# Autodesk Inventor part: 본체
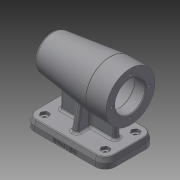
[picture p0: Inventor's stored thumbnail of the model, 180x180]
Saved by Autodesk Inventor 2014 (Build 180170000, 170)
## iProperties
Created: 2017-01
Part Number: 본체
Material: 일반
Document SubType Name: Modeling
Designer: USER
Density: 1 g/cm^3
Appearance: 기본값
Author: USER
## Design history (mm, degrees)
sketch "스케치1"
  geometry: L1 (0, 0)-(112, 0); L2 (112, 0)-(112, -70); L3 (112, -70)-(0, -70); L4 (0, -70)-(0, 0)
  constraints: 8 end point, 2 parallel, 1 horizontal, 1 perpendicular
  dimensions: "d0" = 112 distance of L1.start L1.end; "d1" = 70 distance of L3.end L1.start
extrude "돌출1" new body sketch "스케치1" distance "d2" = 14; taper "d3" = 0 deg
node "작업 평면1"
sketch "스케치3"
  geometry: L1 (0, 74)-(112, 74); L2 (0, 0)-(112, 0) reference; L3 (112, 74)-(112, 108); L4 (112, 108)-(84, 108); L5 (84, 108)-(3.73, 98.144); A1 r 80 centre (80, 74) between (3.73, 98.144) and (0, 74); 1 further point
  constraints: 8 end point, 2 perpendicular, 2 point on circle, 1 centre point, 1 horizontal, 1 point on line, 1 vertical alignment
  dimensions: "d16" = 74 distance between parallel lines of L2 L1; "d17" = 112 distance of L1.start L1.end; "d19" = 7 deg angle of L4 L5; "d20" = 28 distance of L3.end L4.end; "d21" = 68 diameter of L4 L1; "d26" = 80 distance of A1.centre L1.start
revolve "회전1" sketch "스케치3" stored, may be unused: angle "d27" = 90 deg
fillet "모깎기1" dims "d28" = 3
sketch "스케치4"
  geometry: C1 r 34 at (0, 0) reference; C2 r 21 at (0, 0); 1 further point
  constraints: 1 centre point, 1 coincident
  dimensions: "d29" = 42 diameter of C2
extrude "돌출2" cut sketch "스케치4" distance "d30" = 15; taper "d31" = 0 deg
sketch "스케치5"
  geometry: C1 r 21 at (0, 0) reference; C2 r 24 at (0, 0); 1 further point
  constraints: 1 centre point, 1 coincident
  dimensions: "d32" = 48 diameter of C2
extrude "돌출3" cut sketch "스케치5" distance "d33" = 54; taper "d34" = 0 deg
sketch "스케치6"
  geometry: C1 r 24 at (0, 0) reference; C2 r 21 at (0, 0); 1 further point
  constraints: 1 centre point, 1 coincident
  dimensions: "d35" = 42 diameter of C2
extrude "돌출4" cut sketch "스케치6" distance "d36" = 12; taper "d37" = 0 deg
sketch "스케치7"
  geometry: C1 r 21 at (0, 0) reference; C2 r 17.5 at (0, 0); 1 further point
  constraints: 1 centre point, 1 coincident
  dimensions: "d38" = 35 diameter of C2
extrude "돌출5" cut sketch "스케치7" distance "d39" = 18; taper "d40" = 0 deg
sketch "스케치8"
  geometry: C1 r 17.5 at (0, 0) reference; C2 r 16 at (0, 0); 1 further point
  constraints: 1 centre point, 1 coincident
  dimensions: "d41" = 32 diameter of C2
extrude "돌출6" cut sketch "스케치8" distance "d42" = 4; taper "d43" = 0 deg
sketch "스케치9"
  geometry: C1 r 16 at (0, 0) reference; C2 r 10.5 at (0, 0); 1 further point
  constraints: 1 centre point, 1 coincident
  dimensions: "d44" = 21 diameter of C2
extrude "돌출7" cut sketch "스케치9" distance "d45" = 3; taper "d46" = 0 deg
fillet "모깎기2" dims "d47" = 3
fillet "모깎기3" dims "d48" = 0.3
fillet "모깎기4" dims "d49" = 3
node "작업 평면2"
fillet "모깎기8" dims "d130" = 14
chamfer "모따기5" distance "d68" = 1; stored, may be unused: second distance "d69" = 2, angle "d70" = 45 deg
fillet "모깎기6" dims "d71" = 3
fillet "모깎기7" dims "d72" = 3
sketch "스케치14"
  geometry: C1 r 34 at (0, 0) reference; C2 r 22 at (0, 0) reference; A1 r 26 centre (0, 0) between (-26, 0) and (0, -26); 3 further points
  constraints: 4 point on circle, 2 horizontal alignment, 2 vertical alignment, 1 centre point, 1 coincident
  dimensions: "d73" = 52 diameter of A1
hole "구멍1" sketch "스케치14" at (-26, 0), (0, -26), (26, 0), (0, 26) diameter "d74" = 3.242; stored, may be unused: countersink angle "d78" = 90 deg, drill point angle "d80" = 118 deg; dims "d75" = 8, "d76" = 4, "d77" = 2, "d79" = 11
chamfer "모따기6" distance "d131" = 7; stored, may be unused: second distance "d132" = 2, angle "d133" = 15 deg
sketch "스케치22"
  geometry: L1 (14, -1.876)-(98, -1.876) reference; L2 (1.876, -56)-(1.876, -14) reference; L3 (18, -31)-(94, -31); L4 (94, -31)-(94, -39); L5 (94, -39)-(18, -39); L6 (18, -39)-(18, -31); 5 further points
  constraints: 8 end point, 4 midpoint, 2 parallel, 1 horizontal, 1 horizontal alignment, 1 perpendicular, 1 vertical alignment
  dimensions: "d134" = 76 distance of L3.start L3.end; "d135" = 8 distance of L5.end L3.start
extrude "돌출16" join sketch "스케치22" stored distance "d136" = 4; taper "d137" = 0 deg
node "작업 평면8"
sketch "스케치23"
  geometry: L1 (0, -17)-(0, 25) reference; L2 (0, -29.124)-(0, -17) reference; L3 (0, 25)-(0, 37.124) reference; L4 (0, -19)-(-38.397, -12.23); L5 (0, 27)-(-38.15, 20.273); L6 (14, -31)-(7, -31) reference; L7 (7, 39)-(14, 39) reference
  constraints: 4 end point, 2 point on line
  dimensions: "d138" = 12 distance from line of L6 L4.start; "d139" = 100 deg angle of L2 L4; "d140" = 100 deg angle of L3 L5; "d141" = 12 distance from line of L7 L5.start
feature "리브3" dims "d142" = 1, "d143" = 8, "d144" = 0, "d145" = 0, "d146" = 1, "d147" = 1
feature "리브4" dims "d148" = 1, "d149" = 8, "d150" = 0, "d151" = 0, "d152" = 1, "d153" = 1
fillet "모깎기9" dims "d154" = 1
fillet "모깎기10" dims "d155" = 3
fillet "모깎기11" dims "d156" = 3
sketch "스케치25"
  geometry: L1 (16.887, -9)-(19.774, -14); L2 (19.774, -14)-(16.887, -19); L3 (16.887, -19)-(11.113, -19); L4 (11.113, -19)-(8.226, -14); L5 (8.226, -14)-(11.113, -9); L6 (11.113, -9)-(16.887, -9); L7 (92.226, -14)-(95.113, -9); L8 (95.113, -9)-(100.887, -9); L9 (100.887, -9)-(103.774, -14); L10 (103.774, -14)-(100.887, -19); L11 (100.887, -19)-(95.113, -19); L12 (95.113, -19)-(92.226, -14); L13 (100.887, -51)-(103.774, -56); L14 (103.774, -56)-(100.887, -61); L15 (100.887, -61)-(95.113, -61); L16 (95.113, -61)-(92.226, -56); L17 (92.226, -56)-(95.113, -51); L18 (95.113, -51)-(100.887, -51); L19 (19.774, -56)-(16.887, -61); L20 (16.887, -61)-(11.113, -61); L21 (11.113, -61)-(8.226, -56); L22 (8.226, -56)-(11.113, -51); L23 (11.113, -51)-(16.887, -51); L24 (16.887, -51)-(19.774, -56); C1 r 5 at (14, -14); C2 r 5 at (98, -14); C3 r 5 at (14, -56); C4 r 5 at (98, -56); A1 r 11.357 centre (14, -56) between (2.643, -56) and (14, -67.357) reference; A2 r 11.357 centre (98, -56) between (98, -67.357) and (109.357, -56) reference; A3 r 11.357 centre (98, -14) between (109.357, -14) and (98, -2.643) reference; A4 r 11.357 centre (14, -14) between (14, -2.643) and (2.643, -14) reference; 9 further points
  constraints: 48 end point, 8 coincident, 4 centre point, 4 horizontal alignment, 4 midpoint, 4 tangent, 4 vertical alignment, 52 other
  dimensions: "d157" = 10 diameter of C1; "d158" = 10 diameter of C2; "d159" = 10 diameter of C3; "d160" = 10 diameter of C4
extrude "돌출17" cut sketch "스케치25" distance "d161" = 4; taper "d162" = 0 deg
sketch "스케치26"
  geometry: C1 r 2.5 at (-98, -14); C2 r 2.5 at (-14, -14); C3 r 2.5 at (-14, -56); C4 r 2.5 at (-98, -56); A1 r 14 centre (-14, -56) between (-14, -70) and (0, -56) reference; A2 r 14 centre (-14, -14) between (0, -14) and (-14, 0) reference; A3 r 14 centre (-98, -14) between (-98, 0) and (-112, -14) reference; A4 r 14 centre (-98, -56) between (-112, -56) and (-98, -70) reference; 1 further point
  constraints: 4 centre point, 4 coincident
  dimensions: "d163" = 5 diameter of C1; "d164" = 5 diameter of C2; "d165" = 5 diameter of C3; "d166" = 5 diameter of C4
extrude "돌출18" cut sketch "스케치26" stored distance "d167" = 4; taper "d168" = 0 deg
sketch "스케치28"
  geometry: L1 (84, 0)-(0, 0) reference; L2 (0, 13.259)-(84, 13.259) reference; L3 (98, 0)-(98, 7) reference; 2 further points
  constraints: 1 other
  dimensions: "d169" = 4 distance from line of L1 point (42, 4); "d173" = 56 distance from line of L3 point (42, 4)
extrude "돌출19" join sketch "스케치28" distance "d170" = 0.5; taper "d171" = 0 deg
node "솔리드1"
